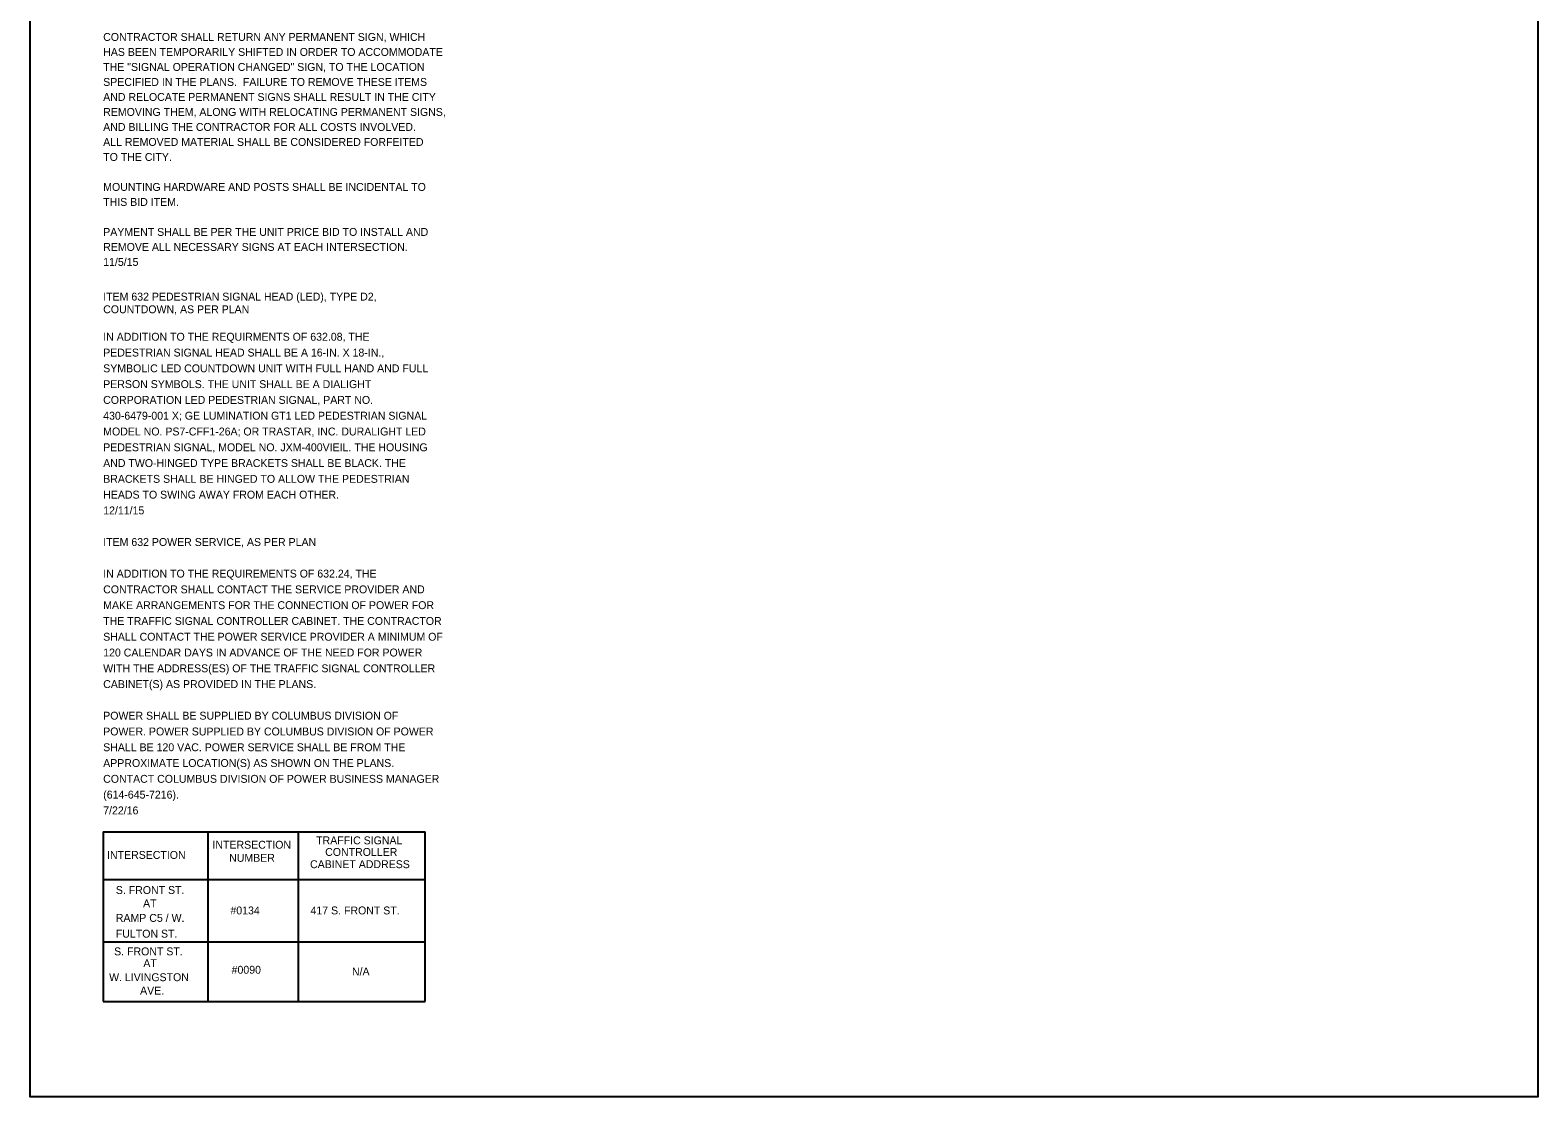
# Model space of a CAD drawing. Extents: x -25.6 to 66.7, y -23.1 to 37.2.
# Drawn here: x 40.01 to 66.75, y -23.15 to -4.23 of the extents above; entities that cross this region are included whole.
import ezdxf

# ---------------------------------------------------------------- set-up
doc = ezdxf.new("R2010")
doc.units = 0
doc.layers.add('SH_Data', color=7, linetype='Continuous')
doc.layers.add('SH_Text', color=7, linetype='Continuous')

msp = doc.modelspace()

# ---------------------------------------------------------------- linework, layer by layer
at = {"layer": 'SH_Text'}
for p, q in [((41.308, -18.445), (41.308, -21.035)), ((41.308, -18.445), (47.018, -18.445)), ((41.308, -18.445), (41.308, -19.195)), ((41.308, -18.445), (42.908, -18.445)), ((43.163, -18.445), (44.763, -18.445)), ((43.163, -18.445), (43.163, -21.035)), ((44.763, -18.445), (44.763, -21.035)), ((47.018, -21.454), (47.018, -18.445)), ((41.308, -19.195), (41.308, -19.295)), ((41.308, -19.295), (41.308, -20.095)), ((41.308, -19.295), (47.018, -19.295)), ((41.308, -20.397), (47.018, -20.397)), ((41.308, -21.035), (41.308, -21.454)), ((43.163, -21.035), (43.163, -21.454)), ((44.763, -21.035), (44.763, -21.454)), ((41.308, -21.454), (47.018, -21.454)), ((44.763, -21.454), (47.018, -21.454))]:
    msp.add_line(p, q, dxfattribs=at)
msp.add_lwpolyline([(40.013, 3.47), (66.746, 3.47), (66.746, -23.147), (40.013, -23.147)], close=True, dxfattribs=at)

# ---------------------------------------------------------------- texts
at = {"layer": 'SH_Data'}
for s, p in [('CONTRACTOR SHALL RETURN ANY PERMANENT SIGN, WHICH ', (41.308, -4.42)), ('HAS BEEN TEMPORARILY SHIFTED IN ORDER TO ACCOMMODATE ', (41.308, -4.686)), ('THE "SIGNAL OPERATION CHANGED" SIGN, TO THE LOCATION ', (41.308, -4.952)), ('SPECIFIED IN THE PLANS.  FAILURE TO REMOVE THESE ITEMS ', (41.308, -5.218)), ('AND RELOCATE PERMANENT SIGNS SHALL RESULT IN THE CITY ', (41.308, -5.484)), ('REMOVING THEM, ALONG WITH RELOCATING PERMANENT SIGNS, ', (41.308, -5.75)), ('AND BILLING THE CONTRACTOR FOR ALL COSTS INVOLVED.  ', (41.308, -6.016)), ('ALL REMOVED MATERIAL SHALL BE CONSIDERED FORFEITED ', (41.308, -6.282)), ('TO THE CITY.', (41.308, -6.548)), ('MOUNTING HARDWARE AND POSTS SHALL BE INCIDENTAL TO ', (41.308, -7.08)), ('THIS BID ITEM.', (41.308, -7.346)), ('PAYMENT SHALL BE PER THE UNIT PRICE BID TO INSTALL AND ', (41.308, -7.878)), ('REMOVE ALL NECESSARY SIGNS AT EACH INTERSECTION.', (41.308, -8.144)), ('11/5/15', (41.308, -8.41)), ('ITEM 632 PEDESTRIAN SIGNAL HEAD (LED), TYPE D2, ', (41.308, -9.025)), ('COUNTDOWN, AS PER PLAN', (41.308, -9.25)), ('IN ADDITION TO THE REQUIRMENTS OF 632.08, THE ', (41.308, -9.737)), ('PEDESTRIAN SIGNAL HEAD SHALL BE A 16-IN. X 18-IN., ', (41.308, -10.017)), ('SYMBOLIC LED COUNTDOWN UNIT WITH FULL HAND AND FULL ', (41.308, -10.297)), ('PERSON SYMBOLS. THE UNIT SHALL BE A DIALIGHT ', (41.308, -10.577)), ('CORPORATION LED PEDESTRIAN SIGNAL, PART NO. ', (41.308, -10.857)), ('430-6479-001 X; GE LUMINATION GT1 LED PEDESTRIAN SIGNAL ', (41.308, -11.137)), ('MODEL NO. PS7-CFF1-26A; OR TRASTAR, INC. DURALIGHT LED ', (41.308, -11.417)), ('PEDESTRIAN SIGNAL, MODEL NO. JXM-400VIEIL. THE HOUSING ', (41.308, -11.697)), ('AND TWO-HINGED TYPE BRACKETS SHALL BE BLACK. THE ', (41.308, -11.977)), ('BRACKETS SHALL BE HINGED TO ALLOW THE PEDESTRIAN ', (41.308, -12.257)), ('HEADS TO SWING AWAY FROM EACH OTHER.', (41.308, -12.537)), ('12/11/15', (41.308, -12.817)), ('ITEM 632 POWER SERVICE, AS PER PLAN', (41.308, -13.377)), ('IN ADDITION TO THE REQUIREMENTS OF 632.24, THE ', (41.308, -13.937)), ('CONTRACTOR SHALL CONTACT THE SERVICE PROVIDER AND ', (41.308, -14.217)), ('MAKE ARRANGEMENTS FOR THE CONNECTION OF POWER FOR ', (41.308, -14.497)), ('THE TRAFFIC SIGNAL CONTROLLER CABINET. THE CONTRACTOR ', (41.308, -14.777)), ('SHALL CONTACT THE POWER SERVICE PROVIDER A MINIMUM OF ', (41.308, -15.057)), ('120 CALENDAR DAYS IN ADVANCE OF THE NEED FOR POWER ', (41.308, -15.337)), ('WITH THE ADDRESS(ES) OF THE TRAFFIC SIGNAL CONTROLLER ', (41.308, -15.617)), ('CABINET(S) AS PROVIDED IN THE PLANS.  ', (41.308, -15.897)), ('POWER SHALL BE SUPPLIED BY COLUMBUS DIVISION OF ', (41.308, -16.457)), ('POWER. POWER SUPPLIED BY COLUMBUS DIVISION OF POWER ', (41.308, -16.737)), ('SHALL BE 120 VAC. POWER SERVICE SHALL BE FROM THE ', (41.308, -17.017)), ('APPROXIMATE LOCATION(S) AS SHOWN ON THE PLANS.  ', (41.308, -17.297)), ('CONTACT COLUMBUS DIVISION OF POWER BUSINESS MANAGER ', (41.308, -17.577)), ('(614-645-7216).', (41.308, -17.857)), ('7/22/16', (41.308, -18.137)), ('INTERSECTION', (43.245, -18.746)), ('TRAFFIC SIGNAL', (45.084, -18.668)), ('INTERSECTION', (41.376, -18.926)), ('NUMBER', (43.541, -18.978)), ('CABINET ADDRESS', (44.976, -19.091)), ('CONTROLLER', (45.244, -18.874)), ('S. FRONT ST. ', (41.532, -19.549)), ('AT', (42.015, -19.785)), ('#0134', (43.564, -19.911)), ('417 S. FRONT ST.', (44.984, -19.911)), ('RAMP C5 / W. ', (41.532, -20.043)), ('FULTON ST. ', (41.532, -20.323)), ('S. FRONT ST. ', (41.502, -20.637)), ('AT', (42.02, -20.846)), ('#0090', (43.585, -20.963)), ('N/A', (45.719, -20.993)), ('W. LIVINGSTON', (41.413, -21.095)), ('AVE.', (41.962, -21.332))]:
    msp.add_text(s, height=0.14, dxfattribs=at).set_placement(p)

doc.saveas('drawing.dxf')
